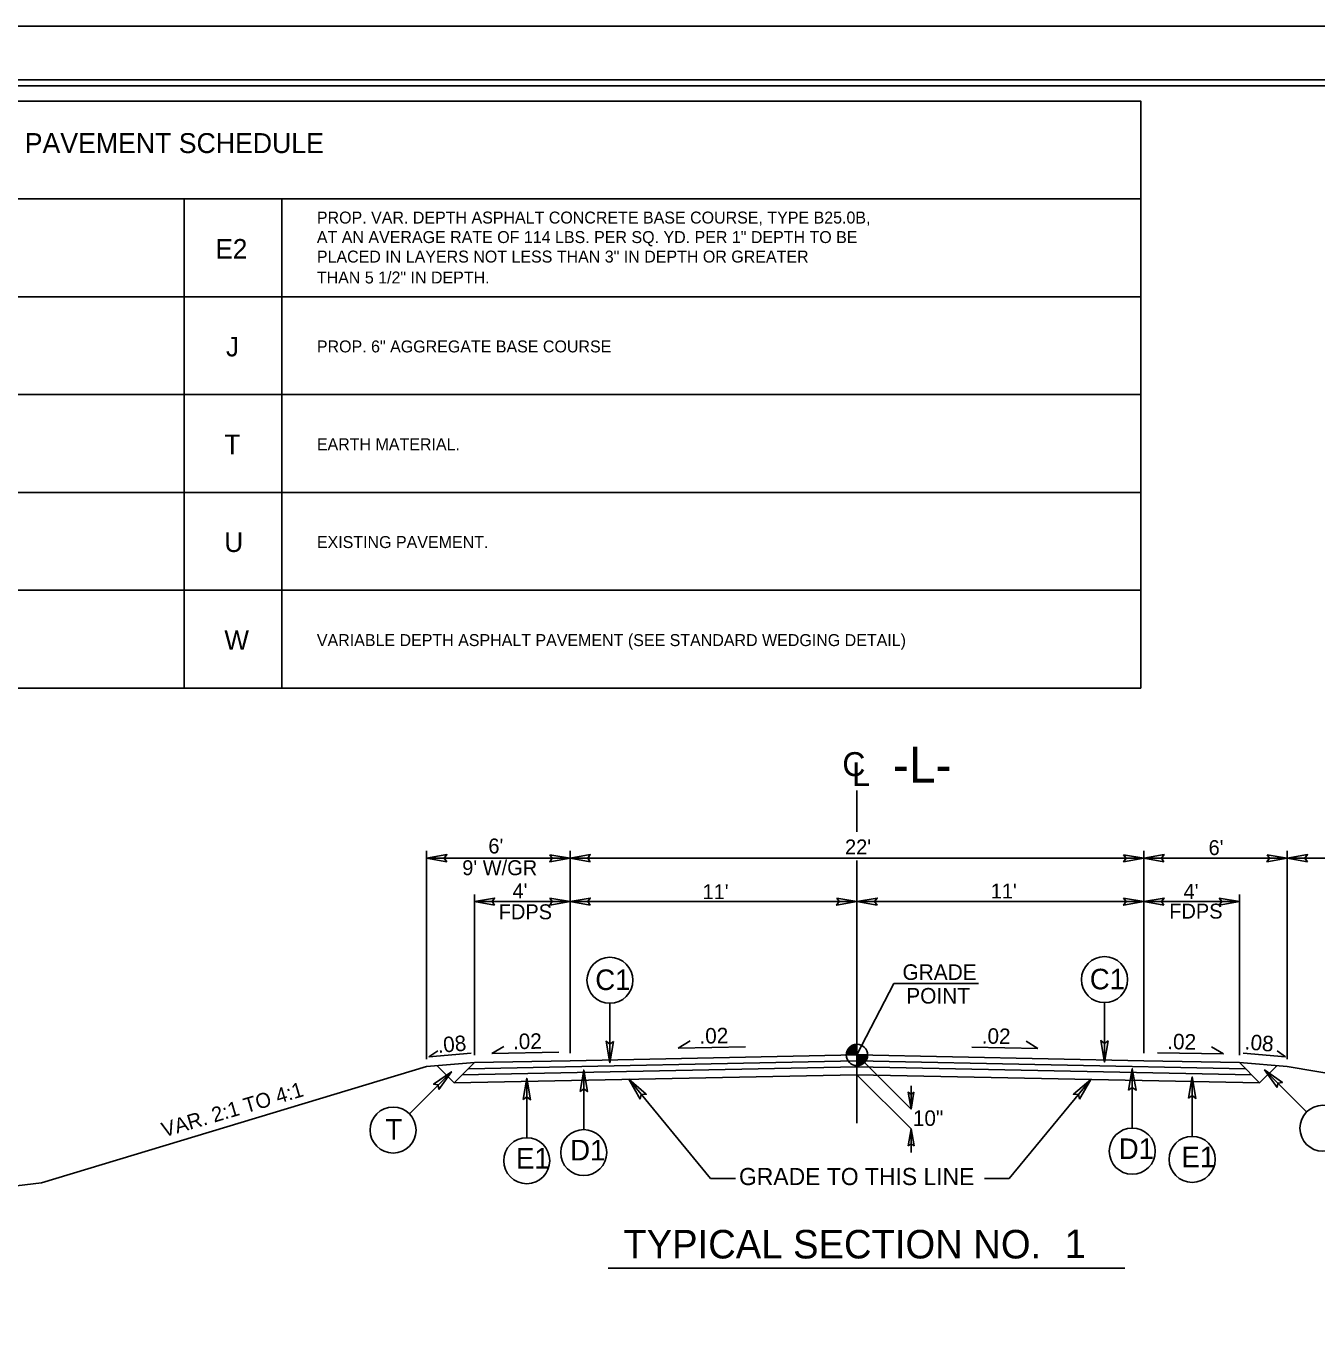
# Model space of a CAD drawing. Extents: x 693533 to 693723, y 486383 to 486493.
# Drawn here: x 693583.4 to 693637.4, y 486438.6 to 486493.3 of the extents above; entities that cross this region are included whole.
import ezdxf

# ---------------------------------------------------------------- set-up
doc = ezdxf.new("R2010")
doc.units = 0
for name, color, linetype in [('Default', 7, 'Continuous'), ('Old_Level_19', 7, 'Continuous'), ('Old_Level_21', 7, 'Continuous'), ('Old_Level_28', 7, 'Continuous'), ('Prop Dimension', 7, 'Continuous'), ('Prop Pavement Schedule Description CELL', 7, 'Continuous'), ('Sheet Cutting Line CELL', 7, 'Continuous'), ('Sheet Plot Border Inside CELL', 7, 'Continuous'), ('Sheet Plot Border Outside CELL', 7, 'Continuous'), ('Sheet Typical CELL', 7, 'Continuous'), ('Typical Grade Point Symbol CELL', 7, 'Continuous'), ('Typical Hinge Slope Arterial CELL', 7, 'Continuous'), ('Typical ID Circle CELL', 7, 'Continuous'), ('Typical Pavement Slope CELL', 7, 'Continuous'), ('Typical Pavement Slope Information CELL', 7, 'Continuous'), ('Typical Shoulder Slope CELL', 7, 'Continuous'), ('Typical Shoulder Slope Information CELL', 7, 'Continuous'), ('Typical Slope Point Local CELL', 7, 'Continuous'), ('Typical Terminator CELL', 7, 'Continuous'), ('Typical Text Centerline CELL', 7, 'Continuous'), ('Typical Text General CELL', 7, 'Continuous'), ('Typical Text Grade Point CELL', 7, 'Continuous'), ('Typical Text ID Circle CELL', 7, 'Continuous'), ('Typical Text Label CELL', 7, 'Continuous')]:
    doc.layers.add(name, color=color, linetype=linetype)

msp = doc.modelspace()

# ---------------------------------------------------------------- linework, layer by layer
at = {"layer": 'Default'}
for p, q in [((693618.164, 486459.622), (693618.164, 486461.339)), ((693600.169, 486450.109), (693600.169, 486458.824)), ((693606.168, 486450.358), (693606.168, 486458.824)), ((693606.168, 486450.358), (693606.168, 486458.824)), ((693630.16, 486450.358), (693630.16, 486458.824)), ((693630.16, 486450.358), (693630.16, 486458.824)), ((693636.159, 486450.109), (693636.159, 486458.824)), ((693606.168, 486458.512), (693600.169, 486458.512)), ((693606.168, 486458.512), (693630.16, 486458.512)), ((693618.164, 486447.43), (693618.164, 486458.414)), ((693630.16, 486458.512), (693636.159, 486458.512)), ((693602.169, 486450.276), (693602.169, 486456.989)), ((693602.169, 486456.696), (693606.168, 486456.696)), ((693606.168, 486450.358), (693606.168, 486457.009)), ((693606.168, 486456.696), (693618.164, 486456.696)), ((693630.16, 486456.696), (693618.164, 486456.696)), ((693630.16, 486450.358), (693630.16, 486457.009)), ((693634.159, 486456.696), (693630.16, 486456.696)), ((693634.159, 486450.276), (693634.159, 486456.989)), ((693606.168, 486450.358), (693606.168, 486455.696)), ((693630.16, 486450.358), (693630.16, 486455.696))]:
    msp.add_line(p, q, dxfattribs=at)
at = {"layer": 'Old_Level_19'}
msp.add_lwpolyline([(693550.034, 486490.177), (693630.033, 486490.177), (693630.033, 486486.086), (693550.034, 486486.086)], close=True, dxfattribs=at)
at = {"layer": 'Old_Level_28'}
for points in [[(693601.013, 486458.366), (693600.169, 486458.512), (693601.018, 486458.662), (693600.91, 486458.512)], [(693605.324, 486458.657), (693606.168, 486458.512), (693605.32, 486458.362), (693605.428, 486458.512)], [(693607.012, 486458.366), (693606.168, 486458.512), (693607.017, 486458.662), (693606.909, 486458.512)], [(693629.316, 486458.657), (693630.16, 486458.512), (693629.311, 486458.362), (693629.419, 486458.512)], [(693631.003, 486458.366), (693630.16, 486458.512), (693631.008, 486458.662), (693630.9, 486458.512)], [(693635.315, 486458.657), (693636.159, 486458.512), (693635.31, 486458.362), (693635.418, 486458.512)], [(693637.002, 486458.366), (693636.159, 486458.512), (693637.007, 486458.662), (693636.899, 486458.512)], [(693603.013, 486456.551), (693602.169, 486456.696), (693603.017, 486456.846), (693602.909, 486456.696)], [(693605.324, 486456.842), (693606.168, 486456.696), (693605.32, 486456.546), (693605.428, 486456.696)], [(693607.012, 486456.551), (693606.168, 486456.696), (693607.017, 486456.846), (693606.909, 486456.696)], [(693617.32, 486456.842), (693618.164, 486456.696), (693617.315, 486456.546), (693617.423, 486456.696)], [(693619.008, 486456.551), (693618.164, 486456.696), (693619.012, 486456.846), (693618.904, 486456.696)], [(693629.316, 486456.842), (693630.16, 486456.696), (693629.311, 486456.546), (693629.419, 486456.696)], [(693631.003, 486456.551), (693630.16, 486456.696), (693631.008, 486456.846), (693630.9, 486456.696)], [(693633.315, 486456.842), (693634.159, 486456.696), (693633.31, 486456.546), (693633.418, 486456.696)]]:
    msp.add_lwpolyline(points, close=True, dxfattribs=at)
at = {"layer": 'Prop Dimension'}
for p, q in [((693636.159, 486450.109), (693636.159, 486458.824)), ((693636.159, 486458.512), (693644.159, 486458.512)), ((693619.705, 486453.266), (693618.164, 486450.285)), ((693620.429, 486448.02), (693618.164, 486450.285)), ((693612.047, 486445.115), (693608.625, 486449.265)), ((693620.429, 486447.191), (693618.164, 486449.456)), ((693620.429, 486448.02), (693620.429, 486448.99)), ((693624.528, 486445.115), (693627.946, 486449.261)), ((693620.429, 486447.191), (693620.429, 486446.202)), ((693612.047, 486445.115), (693613.084, 486445.115)), ((693624.528, 486445.115), (693623.492, 486445.115))]:
    msp.add_line(p, q, dxfattribs=at)
at = {"layer": 'Prop Pavement Schedule Description CELL'}
for points in [[(693554.124, 486481.994), (693550.034, 486481.994), (693550.034, 486486.086), (693590.034, 486486.086), (693590.034, 486481.994), (693554.124, 486481.994), (693554.124, 486486.086)], [(693594.124, 486481.994), (693590.034, 486481.994), (693590.034, 486486.086), (693630.033, 486486.086), (693630.033, 486481.994), (693594.124, 486481.994), (693594.124, 486486.086)], [(693554.124, 486477.902), (693550.034, 486477.902), (693550.034, 486481.994), (693590.034, 486481.994), (693590.034, 486477.902), (693554.124, 486477.902), (693554.124, 486481.994)], [(693594.124, 486477.903), (693590.034, 486477.903), (693590.034, 486481.994), (693630.033, 486481.994), (693630.033, 486477.903), (693594.124, 486477.903), (693594.124, 486481.994)], [(693554.124, 486473.813), (693550.034, 486473.813), (693550.034, 486477.903), (693590.034, 486477.903), (693590.034, 486473.813), (693554.124, 486473.813), (693554.124, 486477.903)], [(693594.124, 486473.813), (693590.034, 486473.813), (693590.034, 486477.903), (693630.033, 486477.903), (693630.033, 486473.813), (693594.124, 486473.813), (693594.124, 486477.903)], [(693554.124, 486469.721), (693550.034, 486469.721), (693550.034, 486473.813), (693590.034, 486473.813), (693590.034, 486469.721), (693554.124, 486469.721), (693554.124, 486473.813)], [(693594.124, 486469.722), (693590.034, 486469.722), (693590.034, 486473.813), (693630.033, 486473.813), (693630.033, 486469.722), (693594.124, 486469.722), (693594.124, 486473.813)], [(693554.124, 486465.631), (693550.034, 486465.631), (693550.034, 486469.722), (693590.034, 486469.722), (693590.034, 486465.631), (693554.124, 486465.631), (693554.124, 486469.722)], [(693594.124, 486465.631), (693590.034, 486465.631), (693590.034, 486469.722), (693630.033, 486469.722), (693630.033, 486465.631), (693594.124, 486465.631), (693594.124, 486469.722)]]:
    msp.add_lwpolyline(points, dxfattribs=at)
at = {"layer": 'Sheet Cutting Line CELL'}
msp.add_line((693701.059, 486493.314), (693532.659, 486493.314), dxfattribs=at)
at = {"layer": 'Sheet Plot Border Inside CELL'}
msp.add_lwpolyline([(693700.609, 486491.069), (693533.959, 486491.069), (693533.959, 486385.559), (693700.609, 486385.559)], close=True, dxfattribs=at)
at = {"layer": 'Sheet Plot Border Outside CELL'}
msp.add_lwpolyline([(693701.059, 486493.314), (693532.659, 486493.314), (693532.659, 486383.314), (693701.059, 486383.314)], close=True, dxfattribs=at)
at = {"layer": 'Sheet Typical CELL'}
msp.add_lwpolyline([(693699.359, 486490.814), (693549.359, 486490.814), (693549.359, 486385.814), (693699.359, 486385.814)], close=True, dxfattribs=at)
at = {"layer": 'Typical Grade Point Symbol CELL'}
for p, q in [((693618.164, 486450.733), (693618.164, 486450.285)), ((693618.164, 486450.285), (693617.716, 486450.285)), ((693618.611, 486450.284), (693618.164, 486450.285)), ((693618.164, 486449.837), (693618.164, 486450.285)), ((693618.164, 486450.285), (693618.611, 486450.284))]:
    msp.add_line(p, q, dxfattribs=at)
for points in [[(693617.858, 486450.611), (693618.164, 486450.611)], [(693617.867, 486450.62), (693618.164, 486450.62)], [(693617.878, 486450.629), (693618.164, 486450.629)], [(693617.889, 486450.638), (693618.164, 486450.638)], [(693617.901, 486450.647), (693618.164, 486450.647)], [(693617.914, 486450.656), (693618.164, 486450.656)], [(693617.928, 486450.665), (693618.164, 486450.665)], [(693617.943, 486450.674), (693618.164, 486450.674)], [(693617.959, 486450.683), (693618.164, 486450.683)], [(693617.978, 486450.692), (693618.164, 486450.692)], [(693617.999, 486450.701), (693618.164, 486450.701)], [(693618.024, 486450.71), (693618.164, 486450.71)], [(693618.054, 486450.719), (693618.164, 486450.719)], [(693618.1, 486450.728), (693618.164, 486450.728)], [(693617.716, 486450.298), (693618.164, 486450.298)], [(693617.716, 486450.289), (693617.716, 486450.289), (693618.164, 486450.289)], [(693617.717, 486450.316), (693618.164, 486450.316)], [(693617.717, 486450.307), (693618.164, 486450.307)], [(693617.718, 486450.325), (693618.164, 486450.325)], [(693617.719, 486450.334), (693618.164, 486450.334)], [(693617.72, 486450.343), (693618.164, 486450.343)], [(693617.721, 486450.352), (693618.164, 486450.352)], [(693617.722, 486450.361), (693618.164, 486450.361)], [(693617.724, 486450.37), (693618.164, 486450.37)], [(693617.726, 486450.379), (693618.164, 486450.379)], [(693617.728, 486450.388), (693618.164, 486450.388)], [(693617.73, 486450.397), (693618.164, 486450.397)], [(693617.733, 486450.405), (693618.164, 486450.405)], [(693617.735, 486450.414), (693618.164, 486450.414)], [(693617.738, 486450.423), (693618.164, 486450.423)], [(693617.741, 486450.432), (693618.164, 486450.432)], [(693617.744, 486450.441), (693618.164, 486450.441)], [(693617.748, 486450.45), (693618.164, 486450.45)], [(693617.752, 486450.459), (693618.164, 486450.459)], [(693617.756, 486450.468), (693618.164, 486450.468)], [(693617.76, 486450.477), (693618.164, 486450.477)], [(693617.764, 486450.486), (693618.164, 486450.486)], [(693617.769, 486450.495), (693618.164, 486450.495)], [(693617.774, 486450.504), (693618.164, 486450.504)], [(693617.779, 486450.513), (693618.164, 486450.513)], [(693617.784, 486450.522), (693618.164, 486450.522)], [(693617.79, 486450.531), (693618.164, 486450.531)], [(693617.796, 486450.54), (693618.164, 486450.54)], [(693617.803, 486450.549), (693618.164, 486450.549)], [(693617.809, 486450.558), (693618.164, 486450.558)], [(693617.816, 486450.567), (693618.164, 486450.567)], [(693617.824, 486450.576), (693618.164, 486450.576)], [(693617.832, 486450.584), (693618.164, 486450.584)], [(693617.84, 486450.593), (693618.164, 486450.593)], [(693617.849, 486450.602), (693618.164, 486450.602)], [(693618.164, 486450.278), (693618.611, 486450.278), (693618.611, 486450.278)], [(693618.164, 486450.269), (693618.611, 486450.269)], [(693618.164, 486450.26), (693618.61, 486450.26)], [(693618.164, 486450.251), (693618.61, 486450.251)], [(693618.164, 486450.242), (693618.609, 486450.242)], [(693618.164, 486450.233), (693618.608, 486450.233)], [(693618.164, 486450.224), (693618.607, 486450.224)], [(693618.164, 486450.215), (693618.605, 486450.215)], [(693618.164, 486450.206), (693618.604, 486450.206)], [(693618.164, 486450.198), (693618.602, 486450.198)], [(693618.164, 486450.189), (693618.601, 486450.189)], [(693618.164, 486450.18), (693618.598, 486450.18)], [(693618.164, 486450.171), (693618.596, 486450.171)], [(693618.164, 486450.162), (693618.594, 486450.162)], [(693618.164, 486450.153), (693618.592, 486450.153)], [(693618.164, 486450.144), (693618.589, 486450.144)], [(693618.164, 486450.135), (693618.586, 486450.135)], [(693618.164, 486450.126), (693618.583, 486450.126)], [(693618.164, 486450.117), (693618.579, 486450.117)], [(693618.164, 486450.108), (693618.575, 486450.108)], [(693618.164, 486450.099), (693618.571, 486450.099)], [(693618.164, 486450.09), (693618.567, 486450.09)], [(693618.164, 486450.081), (693618.563, 486450.081)], [(693618.164, 486450.072), (693618.558, 486450.072)], [(693618.164, 486450.063), (693618.553, 486450.063)], [(693618.164, 486450.054), (693618.548, 486450.054)], [(693618.164, 486450.045), (693618.542, 486450.045)], [(693618.164, 486450.036), (693618.536, 486450.036)], [(693618.164, 486450.027), (693618.53, 486450.027)], [(693618.164, 486450.019), (693618.524, 486450.019)], [(693618.164, 486450.01), (693618.517, 486450.01)], [(693618.164, 486450.001), (693618.51, 486450.001)], [(693618.164, 486449.992), (693618.502, 486449.992)], [(693618.164, 486449.983), (693618.494, 486449.983)], [(693618.164, 486449.974), (693618.486, 486449.974)], [(693618.164, 486449.965), (693618.477, 486449.965)], [(693618.164, 486449.956), (693618.467, 486449.956)], [(693618.164, 486449.947), (693618.457, 486449.947)], [(693618.164, 486449.938), (693618.446, 486449.938)], [(693618.164, 486449.929), (693618.435, 486449.929)], [(693618.164, 486449.92), (693618.423, 486449.92)], [(693618.164, 486449.911), (693618.41, 486449.911)], [(693618.164, 486449.902), (693618.397, 486449.902)], [(693618.164, 486449.893), (693618.381, 486449.893)], [(693618.164, 486449.884), (693618.364, 486449.884)], [(693618.164, 486449.875), (693618.345, 486449.875)], [(693618.164, 486449.866), (693618.324, 486449.866)], [(693618.164, 486449.857), (693618.297, 486449.857)], [(693618.164, 486449.848), (693618.265, 486449.848)], [(693618.164, 486449.84), (693618.213, 486449.84)]]:
    msp.add_lwpolyline(points, dxfattribs=at)
msp.add_circle((693618.164, 486450.285), 0.448, dxfattribs=at)
for start, end in [(89.9905, 179.9905), (269.9905, 359.9905)]:
    msp.add_arc((693618.164, 486450.285), 0.448, start, end, dxfattribs=at)
at = {"layer": 'Typical Hinge Slope Arterial CELL'}
msp.add_line((693644.159, 486448.463), (693636.159, 486449.797), dxfattribs=at)
at = {"layer": 'Typical ID Circle CELL'}
for p, q in [((693607.836, 486452.445), (693607.836, 486449.959)), ((693628.515, 486452.473), (693628.515, 486449.988)), ((693599.45, 486447.823), (693601.208, 486449.58)), ((693606.739, 486447.165), (693606.739, 486449.65)), ((693629.677, 486447.221), (693629.677, 486449.706)), ((693636.969, 486447.899), (693635.21, 486449.657)), ((693604.358, 486446.823), (693604.358, 486449.309)), ((693632.182, 486446.879), (693632.182, 486449.364))]:
    msp.add_line(p, q, dxfattribs=at)
for centre in [(693607.836, 486453.406), (693628.515, 486453.435), (693598.771, 486447.143), (693637.648, 486447.219), (693604.358, 486445.862), (693606.739, 486446.203), (693629.677, 486446.26), (693632.182, 486445.917)]:
    msp.add_circle(centre, 0.962, dxfattribs=at)
at = {"layer": 'Typical Pavement Slope CELL'}
for p, q in [((693606.168, 486450.045), (693618.164, 486450.285)), ((693630.16, 486450.045), (693618.164, 486450.285)), ((693600.611, 486449.833), (693601.325, 486449.119)), ((693602.169, 486449.963), (693601.325, 486449.119)), ((693601.663, 486449.457), (693618.164, 486449.787)), ((693601.916, 486449.71), (693618.164, 486450.035)), ((693634.412, 486449.71), (693618.164, 486450.035)), ((693634.665, 486449.457), (693618.164, 486449.787)), ((693634.159, 486449.963), (693635.003, 486449.119)), ((693635.717, 486449.833), (693635.003, 486449.119)), ((693601.325, 486449.119), (693618.164, 486449.456)), ((693635.003, 486449.119), (693618.164, 486449.456))]:
    msp.add_line(p, q, dxfattribs=at)
at = {"layer": 'Typical Pavement Slope Information CELL'}
for p, q in [((693602.896, 486450.34), (693603.394, 486450.641)), ((693610.692, 486450.573), (693611.191, 486450.874)), ((693610.692, 486450.573), (693613.5, 486450.629)), ((693625.734, 486450.558), (693622.969, 486450.613)), ((693625.734, 486450.558), (693625.238, 486450.858)), ((693633.492, 486450.325), (693632.996, 486450.625)), ((693600.266, 486450.202), (693600.637, 486450.461)), ((693600.266, 486450.202), (693602.039, 486450.354)), ((693602.896, 486450.34), (693605.703, 486450.396)), ((693633.492, 486450.325), (693630.727, 486450.38)), ((693636.086, 486450.202), (693634.313, 486450.354)), ((693636.086, 486450.202), (693635.732, 486450.45))]:
    msp.add_line(p, q, dxfattribs=at)
at = {"layer": 'Typical Shoulder Slope CELL'}
for p, q in [((693600.169, 486449.797), (693602.169, 486449.963)), ((693602.169, 486449.963), (693606.168, 486450.045)), ((693634.159, 486449.963), (693630.16, 486450.045)), ((693636.159, 486449.797), (693634.159, 486449.963))]:
    msp.add_line(p, q, dxfattribs=at)
at = {"layer": 'Typical Slope Point Local CELL'}
msp.add_line((693584.062, 486444.942), (693600.169, 486449.797), dxfattribs=at)
msp.add_lwpolyline([(693584.062, 486444.942), (693583.025, 486444.813)], dxfattribs=at)
at = {"layer": 'Typical Terminator CELL'}
for points in [[(693607.989, 486450.85), (693607.836, 486449.959), (693607.677, 486450.855), (693607.836, 486450.741)], [(693628.668, 486450.878), (693628.515, 486449.988), (693628.356, 486450.883), (693628.515, 486450.769)], [(693600.687, 486448.842), (693601.208, 486449.58), (693600.463, 486449.059), (693600.655, 486449.028)], [(693606.586, 486448.76), (693606.739, 486449.65), (693606.898, 486448.755), (693606.739, 486448.868)], [(693629.524, 486448.816), (693629.677, 486449.706), (693629.836, 486448.811), (693629.677, 486448.925)], [(693635.732, 486448.919), (693635.21, 486449.657), (693635.956, 486449.136), (693635.763, 486449.104)], [(693604.204, 486448.418), (693604.358, 486449.309), (693604.516, 486448.413), (693604.358, 486448.527)], [(693609.097, 486448.44), (693608.625, 486449.265), (693609.353, 486448.644), (693609.149, 486448.631)], [(693627.475, 486448.435), (693627.946, 486449.261), (693627.218, 486448.639), (693627.423, 486448.626)], [(693632.029, 486448.474), (693632.182, 486449.364), (693632.34, 486448.469), (693632.182, 486448.582)], [(693620.55, 486448.723), (693620.429, 486448.02), (693620.304, 486448.727), (693620.429, 486448.637)], [(693620.308, 486446.488), (693620.429, 486447.191), (693620.554, 486446.485), (693620.429, 486446.574)]]:
    msp.add_lwpolyline(points, close=True, dxfattribs=at)
at = {"layer": 'Typical Text Grade Point CELL'}
msp.add_line((693619.705, 486453.266), (693623.243, 486453.266), dxfattribs=at)
at = {"layer": 'Typical Text Label CELL'}
msp.add_line((693607.757, 486441.373), (693629.362, 486441.373), dxfattribs=at)

# ---------------------------------------------------------------- texts
at = {"layer": 'Default'}
for s, p in [("6'", (693602.754, 486458.711)), ("22'", (693617.667, 486458.672)), ("6'", (693632.868, 486458.644)), ("9' W/GR", (693601.662, 486457.803)), ("4'", (693603.765, 486456.834)), ("11'", (693611.709, 486456.801)), ("11'", (693623.76, 486456.829)), ("4'", (693631.824, 486456.812)), ('FDPS', (693603.187, 486455.959)), ('FDPS', (693631.223, 486455.987))]:
    msp.add_text(s, height=0.6249, dxfattribs=at).set_placement(p)
msp.add_text('VAR. 2:1 TO 4:1', height=0.6249, rotation=16.4567, dxfattribs=at).set_placement((693589.195, 486446.834))
at = {"layer": 'Old_Level_21'}
msp.add_text('PAVEMENT SCHEDULE', height=0.83333, dxfattribs=at).set_placement((693583.369, 486488.006))
at = {"layer": 'Prop Dimension'}
msp.add_text('10"', height=0.6476, rotation=0, dxfattribs=at).set_placement((693620.504, 486447.317))
at = {"layer": 'Prop Pavement Schedule Description CELL'}
for s, height, p in [('PROP. VAR. DEPTH ASPHALT CONCRETE BASE COURSE, TYPE B25.0B, ', 0.5, (693595.583, 486485.058)), ('AT AN AVERAGE RATE OF 114 LBS. PER SQ. YD. PER 1" DEPTH TO BE', 0.5, (693595.583, 486484.242)), ('E2', 0.8167, (693591.34, 486483.594)), ('PLACED IN LAYERS NOT LESS THAN 3" IN DEPTH OR GREATER', 0.5, (693595.583, 486483.426)), ('THAN 5 1/2" IN DEPTH.', 0.5, (693595.583, 486482.551)), ('J', 0.817, (693591.783, 486479.502)), ('PROP. 6" AGGREGATE BASE COURSE', 0.5, (693595.583, 486479.668)), ('T', 0.817, (693591.715, 486475.412)), ('EARTH MATERIAL.', 0.5, (693595.583, 486475.577)), ('U', 0.817, (693591.715, 486471.321)), ('EXISTING PAVEMENT.', 0.5, (693595.583, 486471.486)), ('W', 0.817, (693591.714, 486467.23)), ('VARIABLE DEPTH ASPHALT PAVEMENT (SEE STANDARD WEDGING DETAIL)', 0.5, (693595.583, 486467.385))]:
    msp.add_text(s, height=height, dxfattribs=at).set_placement(p)
at = {"layer": 'Typical Shoulder Slope Information CELL'}
for s, rotation, p in [('.02', 1.1457, (693603.79, 486450.522)), ('.02', 1.1457, (693611.586, 486450.754)), ('.02', 358.8543, (693623.378, 486450.762)), ('.02', 358.8543, (693631.135, 486450.529)), ('.08', 4.8901, (693600.653, 486450.365)), ('.08', 355.1099, (693634.36, 486450.521))]:
    msp.add_text(s, height=0.6476, rotation=rotation, dxfattribs=at).set_placement(p)
at = {"layer": 'Typical Text Centerline CELL'}
msp.add_text('C', height=1, dxfattribs=at).set_placement((693617.554, 486461.949))
msp.add_text('L', height=1, rotation=359.9469, dxfattribs=at).set_placement((693617.963, 486461.529))
at = {"layer": 'Typical Text General CELL'}
msp.add_text('GRADE TO THIS LINE', height=0.71614, dxfattribs=at).set_placement((693613.233, 486444.842))
at = {"layer": 'Typical Text Grade Point CELL'}
for s, p in [('GRADE', (693620.069, 486453.422)), ('POINT', (693620.226, 486452.433))]:
    msp.add_text(s, height=0.6525, dxfattribs=at).set_placement(p)
at = {"layer": 'Typical Text ID Circle CELL'}
for s, height, p in [('C1', 0.8608, (693627.902, 486453.028)), ('C1', 0.8608, (693607.223, 486453)), ('T', 0.861, (693598.449, 486446.747)), ('D1', 0.8608, (693629.112, 486445.93)), ('E1', 0.8608, (693603.909, 486445.532)), ('D1', 0.8608, (693606.174, 486445.873)), ('E1', 0.8608, (693631.734, 486445.587))]:
    msp.add_text(s, height=height, dxfattribs=at).set_placement(p)
at = {"layer": 'Typical Text Label CELL'}
for s, height, p in [('-L-', 1.5, (693619.672, 486461.673)), ('TYPICAL SECTION NO.  ', 1.19356, (693608.398, 486441.773)), ('1', 1.194, (693626.85, 486441.789))]:
    msp.add_text(s, height=height, dxfattribs=at).set_placement(p)

doc.saveas('drawing.dxf')
